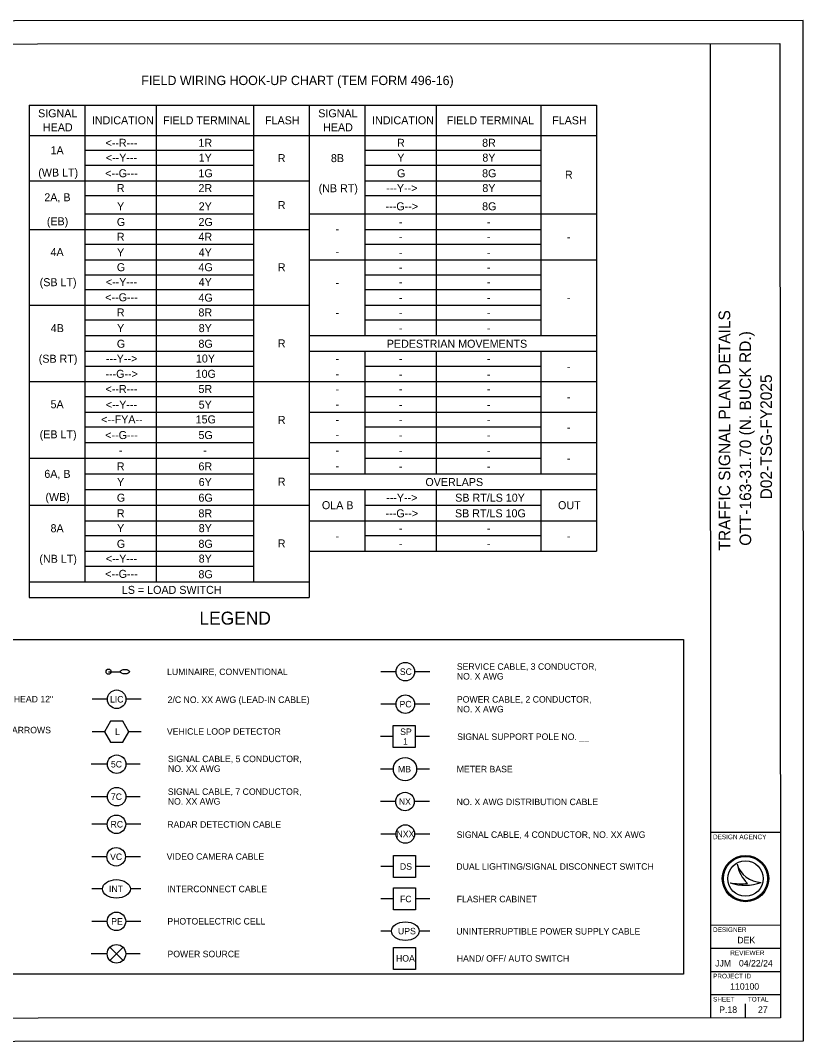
# Model space of a CAD drawing. Extents: x 0 to 680, y 0 to 440.
# Drawn here: x 342.6 to 680.1, y -0.1 to 440.2 of the extents above; entities that cross this region are included whole.
import ezdxf

# ---------------------------------------------------------------- set-up
doc = ezdxf.new("R2010")
doc.units = 0
for name, color, linetype in [('Default', 7, 'Continuous'), ('LT_P_Luminaires', 7, 'Continuous'), ('SG_P_Text', 7, 'Continuous'), ('SH_Border', 7, 'Continuous'), ('SH_Cut_Line', 7, 'Continuous'), ('SH_Data', 7, 'Continuous'), ('SH_Text', 7, 'Continuous')]:
    doc.layers.add(name, color=color, linetype=linetype)

msp = doc.modelspace()

# ---------------------------------------------------------------- linework, layer by layer
at = {"layer": 'Default'}
for p, q in [((346.31, 403.66), (590.81, 403.66)), ((346.31, 403.66), (346.31, 191.41)), ((370.31, 403.66), (370.31, 198.16)), ((401.06, 403.66), (401.06, 198.16)), ((443.06, 403.66), (443.06, 198.16)), ((467.06, 403.66), (467.06, 191.41)), ((491.06, 403.66), (491.06, 304.28)), ((521.81, 403.66), (521.81, 304.28)), ((566.81, 403.66), (566.81, 304.28)), ((590.81, 403.66), (590.81, 211.28)), ((346.31, 390.53), (590.81, 390.53)), ((370.31, 384.16), (443.06, 384.16)), ((491.06, 384.16), (566.81, 384.16)), ((370.31, 377.78), (443.06, 377.78)), ((491.06, 377.78), (566.81, 377.78)), ((346.31, 371.03), (467.06, 371.03)), ((491.06, 371.03), (566.81, 371.03)), ((370.31, 364.66), (443.06, 364.66)), ((491.06, 364.66), (566.81, 364.66)), ((370.31, 356.78), (443.06, 356.78)), ((467.06, 356.78), (590.81, 356.78)), ((346.31, 350.03), (467.06, 350.03)), ((491.06, 350.03), (566.81, 350.03)), ((370.31, 343.66), (443.06, 343.66)), ((491.06, 343.66), (566.81, 343.66)), ((370.31, 336.91), (443.06, 336.91)), ((467.06, 336.91), (590.81, 336.91)), ((370.31, 330.53), (443.06, 330.53)), ((491.06, 330.53), (566.81, 330.53)), ((370.31, 324.16), (443.06, 324.16)), ((491.06, 324.16), (566.81, 324.16)), ((346.31, 317.41), (467.06, 317.41)), ((491.06, 317.41), (566.81, 317.41)), ((370.31, 311.03), (443.06, 311.03)), ((491.06, 311.03), (566.81, 311.03)), ((370.31, 304.28), (443.06, 304.28)), ((467.06, 304.28), (590.81, 304.28)), ((370.31, 297.53), (443.06, 297.53)), ((467.06, 297.53), (590.81, 297.53)), ((491.06, 297.53), (491.06, 244.66)), ((521.81, 297.53), (521.81, 244.66)), ((566.81, 297.53), (566.81, 244.66)), ((370.31, 291.16), (443.06, 291.16)), ((491.06, 291.16), (566.81, 291.16)), ((346.31, 284.41), (590.81, 284.41)), ((370.31, 278.03), (443.06, 278.03)), ((491.06, 278.03), (566.81, 278.03)), ((370.31, 271.28), (443.06, 271.28)), ((467.06, 271.28), (590.81, 271.28)), ((370.31, 264.91), (443.06, 264.91)), ((491.06, 264.91), (566.81, 264.91)), ((370.31, 258.16), (443.06, 258.16)), ((467.06, 258.16), (590.81, 258.16)), ((346.31, 251.41), (467.06, 251.41)), ((491.06, 251.41), (566.81, 251.41)), ((370.31, 244.66), (443.06, 244.66)), ((467.06, 244.66), (590.81, 244.66)), ((370.31, 237.91), (443.06, 237.91)), ((467.06, 237.91), (590.81, 237.91)), ((491.06, 237.91), (491.06, 211.28)), ((521.81, 237.91), (521.81, 211.28)), ((566.81, 237.91), (566.81, 211.28)), ((346.31, 231.16), (467.06, 231.16)), ((491.06, 231.16), (566.81, 231.16)), ((370.31, 224.41), (443.06, 224.41)), ((467.06, 224.41), (521.81, 224.41)), ((521.81, 224.41), (566.81, 224.41)), ((566.81, 224.41), (590.81, 224.41)), ((370.31, 218.03), (443.06, 218.03)), ((491.06, 218.03), (566.81, 218.03)), ((370.31, 211.28), (443.06, 211.28)), ((467.06, 211.28), (590.81, 211.28)), ((370.31, 204.91), (443.06, 204.91)), ((346.31, 198.16), (467.06, 198.16)), ((346.31, 191.41), (467.06, 191.41))]:
    msp.add_line(p, q, dxfattribs=at)
at = {"layer": 'LT_P_Luminaires'}
msp.add_line((380.58, 159.37), (385.58, 159.37), dxfattribs=at)
msp.add_circle((380.58, 159.37), 1.1, dxfattribs=at)
msp.add_ellipse((387.58, 159.37), major_axis=(2, 0), ratio=0.5, dxfattribs=at)
at = {"layer": 'SG_P_Text'}
for p, q in [((504.45, 159.37), (497.91, 159.37)), ((518.99, 159.37), (512.45, 159.37)), ((380.04, 147.47), (373.5, 147.47)), ((394.58, 147.47), (388.04, 147.47)), ((504.45, 145.37), (497.91, 145.37)), ((518.99, 145.37), (512.45, 145.37)), ((378.85, 133.47), (373.5, 133.47)), ((394.58, 133.47), (389.24, 133.47)), ((503.25, 131.37), (497.78, 131.37)), ((518.86, 131.37), (512.73, 131.37)), ((380.04, 119.47), (373.13, 119.47)), ((394.21, 119.47), (388.04, 119.47)), ((503.32, 117.37), (497.78, 117.37)), ((518.86, 117.37), (513.32, 117.37)), ((380.04, 105.47), (373.13, 105.47)), ((394.21, 105.47), (388.04, 105.47)), ((504.32, 103.37), (497.78, 103.37)), ((518.86, 103.37), (512.32, 103.37)), ((379.95, 93.57), (373.41, 93.57)), ((394.49, 93.57), (387.95, 93.57)), ((504.46, 89.37), (497.92, 89.37)), ((519.01, 89.37), (512.46, 89.37)), ((379.82, 79.57), (373.28, 79.57)), ((394.36, 79.57), (387.82, 79.57)), ((503.4, 75.37), (497.92, 75.37)), ((519.01, 75.37), (512.87, 75.37)), ((377.95, 65.71), (373.41, 65.71)), ((394.49, 65.71), (389.95, 65.71)), ((503.4, 61.37), (497.92, 61.37)), ((519.01, 61.37), (512.87, 61.37)), ((379.95, 51.71), (373.41, 51.71)), ((394.49, 51.71), (387.95, 51.71)), ((502.46, 47.51), (497.92, 47.51)), ((519.01, 47.51), (514.46, 47.51)), ((381.12, 40.54), (386.78, 34.88)), ((381.12, 34.88), (386.78, 40.54)), ((379.95, 37.71), (373.04, 37.71)), ((394.12, 37.71), (387.95, 37.71))]:
    msp.add_line(p, q, dxfattribs=at)
for points in [[(389.24, 133.47), (386.64, 137.97), (381.44, 137.97), (378.85, 133.47), (381.44, 128.97), (386.64, 128.97)], [(503.25, 136.11), (512.73, 136.11), (512.73, 126.64), (503.25, 126.64)], [(503.4, 80.11), (512.87, 80.11), (512.87, 70.64), (503.4, 70.64)], [(503.4, 66.11), (512.87, 66.11), (512.87, 56.64), (503.4, 56.64)], [(503.4, 40.5), (512.87, 40.5), (512.87, 31.03), (503.4, 31.03)]]:
    msp.add_lwpolyline(points, close=True, dxfattribs=at)
for centre, radius in [((508.45, 159.37), 4), ((384.04, 147.47), 4), ((508.45, 145.37), 4), ((384.04, 119.47), 4), ((508.32, 117.37), 5), ((384.04, 105.47), 4), ((508.32, 103.37), 4), ((383.95, 93.57), 4), ((508.46, 89.37), 4), ((383.82, 79.57), 4), ((383.95, 51.71), 4), ((383.95, 37.71), 4)]:
    msp.add_circle(centre, radius, dxfattribs=at)
for centre in [(383.95, 65.71), (508.46, 47.51)]:
    msp.add_ellipse(centre, major_axis=(6, 0), ratio=0.666667, dxfattribs=at)
at = {"layer": 'SH_Border'}
for p, q in [((640.08, 10.14), (639.92, 430.14)), ((640.05, 90.14), (670.05, 90.15)), ((640.07, 50.14), (670.07, 50.15)), ((640.07, 40.14), (670.07, 40.15)), ((640.07, 30.14), (670.07, 30.15)), ((640.08, 20.14), (670.08, 20.15))]:
    msp.add_line(p, q, dxfattribs=at)
msp.add_lwpolyline([(29.92, 429.9), (669.92, 430.15), (670.08, 10.15), (30.08, 9.9)], close=True, dxfattribs=at)
at = {"layer": 'SH_Cut_Line'}
msp.add_lwpolyline([(0.09, -0.11), (680.09, 0.16), (679.91, 440.16), (-0.09, 439.89)], close=True, dxfattribs=at)
at = {"layer": 'SH_Data'}
for p, q in [((651.41, 76.34), (651.41, 76.34)), ((648.4, 68.33), (648.4, 68.33)), ((655.06, 70.15), (655.06, 70.15)), ((661.8, 68.52), (661.81, 68.52)), ((647.58, 13.64), (647.58, 13.64)), ((655.08, 10.15), (655.08, 16.15))]:
    msp.add_line(p, q, dxfattribs=at)
for radius in [10, 9.54, 9.54, 7.64]:
    msp.add_circle((655.06, 70.15), radius, dxfattribs=at)
for centre, radius, start, end in [((662.37, 80.1), 11.6, 198.9484, 198.9547), ((666.99, 79.55), 15.91, 191.6606, 191.6649), ((662.37, 80.1), 11.6, 198.9547, 267.1884), ((666.99, 79.55), 15.91, 191.6649, 226.1174), ((654.84, 87.55), 20.26, 251.4804, 290.106), ((653.01, 93.23), 25.32, 259.5191, 259.5222), ((654.84, 87.55), 20.26, 251.4755, 251.4804), ((653.01, 93.23), 25.32, 259.5222, 276.6899)]:
    msp.add_arc(centre, radius, start, end, dxfattribs=at)
at = {"layer": 'SH_Text'}
msp.add_lwpolyline([(231.79, 173.25), (628.35, 173.25), (628.35, 29), (231.79, 29)], close=True, dxfattribs=at)

# ---------------------------------------------------------------- texts
at = {"layer": 'Default'}
for s, p in [('SIGNAL ', (350.18, 398.39)), ('SIGNAL ', (470.93, 398.39)), ('INDICATION', (373.37, 395.37)), ('FIELD TERMINAL', (404.05, 395.37)), ('FLASH', (448, 395.37)), ('INDICATION', (494.12, 395.37)), ('FIELD TERMINAL', (526.3, 395.37)), ('FLASH', (571.75, 395.37)), ('HEAD', (352.27, 392.35)), ('HEAD', (473.02, 392.35)), ('<--R---', (379.26, 385.66)), ('1R', (419.3, 385.66)), ('R', (504.88, 385.66)), ('8R', (541.55, 385.66)), ('1A', (355.55, 382.43)), ('<--Y---', (379.38, 379.28)), ('1Y', (419.4, 379.28)), ('R', (453.5, 379.06)), ('8B', (476.39, 379.06)), ('Y', (504.98, 379.28)), ('8Y', (541.65, 379.28)), ('(WB LT)', (350.27, 372.83)), ('<--G---', (379.14, 372.53)), ('1G', (419.3, 372.53)), ('G', (504.88, 372.53)), ('8G', (541.55, 372.53)), ('R', (577.25, 371.93)), ('2A, B', (352.87, 362.18)), ('R', (384.13, 366.16)), ('2R', (419.3, 366.16)), ('(NB RT)', (471.1, 366.08)), ('---Y-->', (500.21, 366.16)), ('8Y', (541.65, 366.16)), ('Y', (384.23, 358.28)), ('2Y', (419.4, 358.28)), ('R', (453.5, 358.81)), ('---G-->', (499.97, 358.28)), ('8G', (541.55, 358.28)), ('(EB)', (353.96, 351.83)), ('G', (384.13, 351.53)), ('2G', (419.3, 351.53)), ('-', (505.73, 351.53)), ('-', (543.6, 351.53)), ('R', (384.13, 345.16)), ('4R', (419.3, 345.16)), ('-', (478.35, 348.5)), ('-', (505.73, 345.16)), ('-', (543.6, 345.16)), ('-', (578.1, 345.12)), ('4A', (355.55, 338.56)), ('Y', (384.23, 338.41)), ('4Y', (419.4, 338.41)), ('-', (478.35, 338.71)), ('-', (505.73, 338.41)), ('-', (543.6, 338.41)), ('G', (384.13, 332.03)), ('4G', (419.3, 332.03)), ('R', (453.5, 332)), ('-', (505.73, 332.03)), ('-', (543.6, 332.03)), ('(SB LT)', (350.87, 325.58)), ('<--Y---', (379.38, 325.66)), ('4Y', (419.4, 325.66)), ('-', (478.35, 325.43)), ('-', (505.73, 325.66)), ('-', (543.6, 325.66)), ('<--G---', (379.14, 319.06)), ('4G', (419.3, 318.91)), ('-', (505.73, 318.91)), ('-', (543.6, 318.91)), ('-', (578.1, 318.87)), ('R', (384.13, 312.53)), ('8R', (419.3, 312.53)), ('-', (478.35, 312.46)), ('-', (505.73, 312.53)), ('-', (543.6, 312.53)), ('4B', (355.64, 305.75)), ('Y', (384.23, 305.78)), ('8Y', (419.4, 305.78)), ('-', (505.73, 305.78)), ('-', (543.6, 305.78)), ('G', (384.13, 299.03)), ('8G', (419.3, 299.03)), ('R', (453.5, 299.18)), ('PEDESTRIAN MOVEMENTS', (500.47, 299.03)), ('(SB RT)', (350.47, 292.58)), ('---Y-->', (379.46, 292.66)), ('10Y', (418.2, 292.66)), ('-', (478.35, 292.62)), ('-', (505.73, 292.66)), ('-', (543.6, 292.66)), ('-', (578.1, 289.25)), ('---G-->', (379.22, 286.06)), ('10G', (418.09, 286.06)), ('-', (478.35, 286.06)), ('-', (505.73, 285.91)), ('-', (543.6, 285.91)), ('<--R---', (379.26, 279.53)), ('5R', (419.3, 279.53)), ('-', (478.35, 279.5)), ('-', (505.73, 279.53)), ('-', (543.6, 279.53)), ('-', (578.1, 276.12)), ('5A', (355.55, 272.93)), ('<--Y---', (379.38, 272.78)), ('5Y', (419.4, 272.78)), ('-', (478.35, 272.93)), ('-', (505.73, 272.78)), ('-', (543.6, 272.78)), ('<--FYA--', (377.41, 266.41)), ('15G', (418.09, 266.41)), ('R', (453.5, 266.18)), ('-', (478.35, 266.37)), ('-', (505.73, 266.41)), ('-', (543.6, 266.41)), ('-', (578.1, 263)), ('(EB LT)', (350.87, 259.96)), ('<--G---', (379.14, 259.66)), ('5G', (419.3, 259.66)), ('-', (478.35, 259.81)), ('-', (505.73, 259.66)), ('-', (543.6, 259.66)), ('-', (384.98, 253.06)), ('-', (421.35, 253.06)), ('-', (478.35, 253.06)), ('-', (505.73, 252.91)), ('-', (543.6, 252.91)), ('-', (578.1, 249.68)), ('R', (384.13, 246.16)), ('6R', (419.3, 246.16)), ('-', (478.35, 246.31)), ('-', (505.73, 246.16)), ('-', (543.6, 246.16)), ('6A, B', (352.87, 242.93)), ('Y', (384.23, 239.41)), ('6Y', (419.4, 239.41)), ('R', (453.5, 239.56)), ('OVERLAPS', (517.11, 239.41)), ('(WB)', (353.36, 232.96)), ('G', (384.13, 232.66)), ('6G', (419.3, 232.66)), ('---Y-->', (500.21, 232.66)), ('SB RT/LS 10Y', (529.96, 232.66)), ('R', (384.13, 225.91)), ('8R', (419.3, 225.91)), ('OLA B', (472.5, 229.43)), ('---G-->', (499.97, 225.91)), ('SB RT/LS 10G', (529.86, 225.91)), ('OUT', (574.28, 229.43)), ('8A', (355.55, 219.5)), ('Y', (384.23, 219.53)), ('8Y', (419.4, 219.53)), ('-', (505.73, 219.53)), ('-', (543.6, 219.53)), ('G', (384.13, 212.78)), ('8G', (419.3, 212.78)), ('R', (453.5, 212.93)), ('-', (478.35, 216.12)), ('-', (578.1, 216.12)), ('-', (505.73, 212.78)), ('-', (543.6, 212.78)), ('(NB LT)', (350.75, 206.33)), ('<--Y---', (379.38, 206.41)), ('8Y', (419.4, 206.41)), ('<--G---', (379.14, 199.81)), ('8G', (419.3, 199.66)), ('LS = LOAD SWITCH', (386.3, 192.91))]:
    msp.add_text(s, height=3.45, dxfattribs=at).set_placement(p)
at = {"layer": 'SG_P_Text'}
for s, p in [('SC', (506.09, 157.97)), ('LIC', (381.19, 146.07)), ('PC', (505.95, 143.97)), ('L', (383.35, 132.07)), ('SP', (506.22, 132.07)), ('1', (507.45, 127.87)), ('5C', (381.56, 118.07)), ('MB', (505.3, 115.97)), ('7C', (381.56, 104.07)), ('NX', (505.65, 101.97)), ('RC', (381.41, 92.17)), ('NXX', (504.65, 87.97)), ('VC', (381.22, 78.17)), ('DS', (506.12, 73.97)), ('INT', (380.75, 64.31)), ('FC', (506.15, 59.97)), ('PE', (381.7, 50.31)), ('UPS', (505.29, 46.11)), ('HOA', (504.44, 34.37))]:
    msp.add_text(s, height=2.8, dxfattribs=at).set_placement(p)
at = {"layer": 'SH_Data'}
for s, height, rotation, p in [('TRAFFIC SIGNAL PLAN DETAILS', 5, 90.0227, (648.5, 211.59)), ('OTT-163-31.70 (N. BUCK RD.)', 5, 90.0227, (657.5, 213.66)), ('D02-TSG-FY2025', 5, 90.0227, (666.49, 233.65)), ('DESIGN AGENCY', 2, 0.0227, (641.05, 87.14)), ('DESIGNER', 2, 0.0227, (641.07, 47.14)), ('DEK', 2.8, 0.0227, (651.54, 42.25)), ('REVIEWER', 2, 0.0227, (648.51, 37.14)), ('JJM', 2.8, 0.0227, (641.97, 32.24)), ('04/22/24', 2.8, 0.0227, (652.23, 32.25)), ('PROJECT ID', 2, 0.0227, (641.08, 27.14)), ('110100', 2.8, 0.0227, (648.45, 22.24)), ('SHEET', 2, 0.0227, (641.08, 17.14)), ('TOTAL', 2, 0.0227, (656.08, 17.15)), ('P.18', 2.8, 0.0227, (643.74, 12.24)), ('27', 2.8, 0.0227, (660.45, 12.25))]:
    msp.add_text(s, height=height, rotation=rotation, dxfattribs=at).set_placement(p)
at = {"layer": 'SH_Text'}
for s, height, p in [('FIELD WIRING HOOK-UP CHART (TEM FORM 496-16)', 4, (394.66, 412.28)), ('LEGEND', 5.6, (419.71, 179.65)), ('SERVICE CABLE, 3 CONDUCTOR,', 2.8, (530.65, 160.18)), ('LUMINAIRE, CONVENTIONAL', 2.8, (405.78, 157.9)), ('NO. X AWG', 2.8, (530.65, 155.98)), ('TRAFFIC SIGNAL, 2 UNIT, 3 UNIT, OR PHB HEAD 12"', 2.8, (263.78, 146.14)), ('2/C NO. XX AWG (LEAD-IN CABLE)', 2.8, (406.01, 145.89)), ('POWER CABLE, 2 CONDUCTOR,', 2.8, (530.68, 146.03)), ('NO. X AWG', 2.8, (530.68, 141.83)), ('TRAFFIC SIGNAL, 3 UNIT HEAD, 12" WITH ARROWS', 2.8, (263.7, 132.8)), ('VEHICLE LOOP DETECTOR', 2.8, (405.7, 132.19)), ('SIGNAL SUPPORT POLE NO. __', 2.8, (530.79, 129.94)), ('SIGNAL CABLE, 5 CONDUCTOR, ', 2.8, (406.16, 120.37)), ('NO. XX AWG', 2.8, (406.16, 116.17)), ('METER BASE', 2.8, (530.6, 115.98)), ('SIGNAL CABLE, 7 CONDUCTOR, ', 2.8, (406.08, 106.24)), ('NO. XX AWG', 2.8, (406.08, 102.04)), ('NO. X AWG DISTRIBUTION CABLE', 2.8, (530.56, 101.83)), ('RADAR DETECTION CABLE', 2.8, (405.85, 92.09)), ('SIGNAL CABLE, 4 CONDUCTOR, NO. XX AWG', 2.8, (530.59, 87.71)), ('VIDEO CAMERA CABLE', 2.8, (405.59, 78.28)), ('DUAL LIGHTING/SIGNAL DISCONNECT SWITCH', 2.8, (530.44, 73.98)), ('INTERCONNECT CABLE', 2.8, (405.82, 64.28)), ('FLASHER CABINET', 2.8, (530.63, 59.94)), ('PHOTOELECTRIC CELL', 2.8, (405.89, 50.35)), ('UNINTERRUPTIBLE POWER SUPPLY CABLE', 2.8, (530.43, 46.01)), ('POWER SOURCE', 2.8, (405.94, 36.25)), ('HAND/ OFF/ AUTO SWITCH', 2.8, (530.63, 34.33))]:
    msp.add_text(s, height=height, dxfattribs=at).set_placement(p)

doc.saveas('drawing.dxf')
